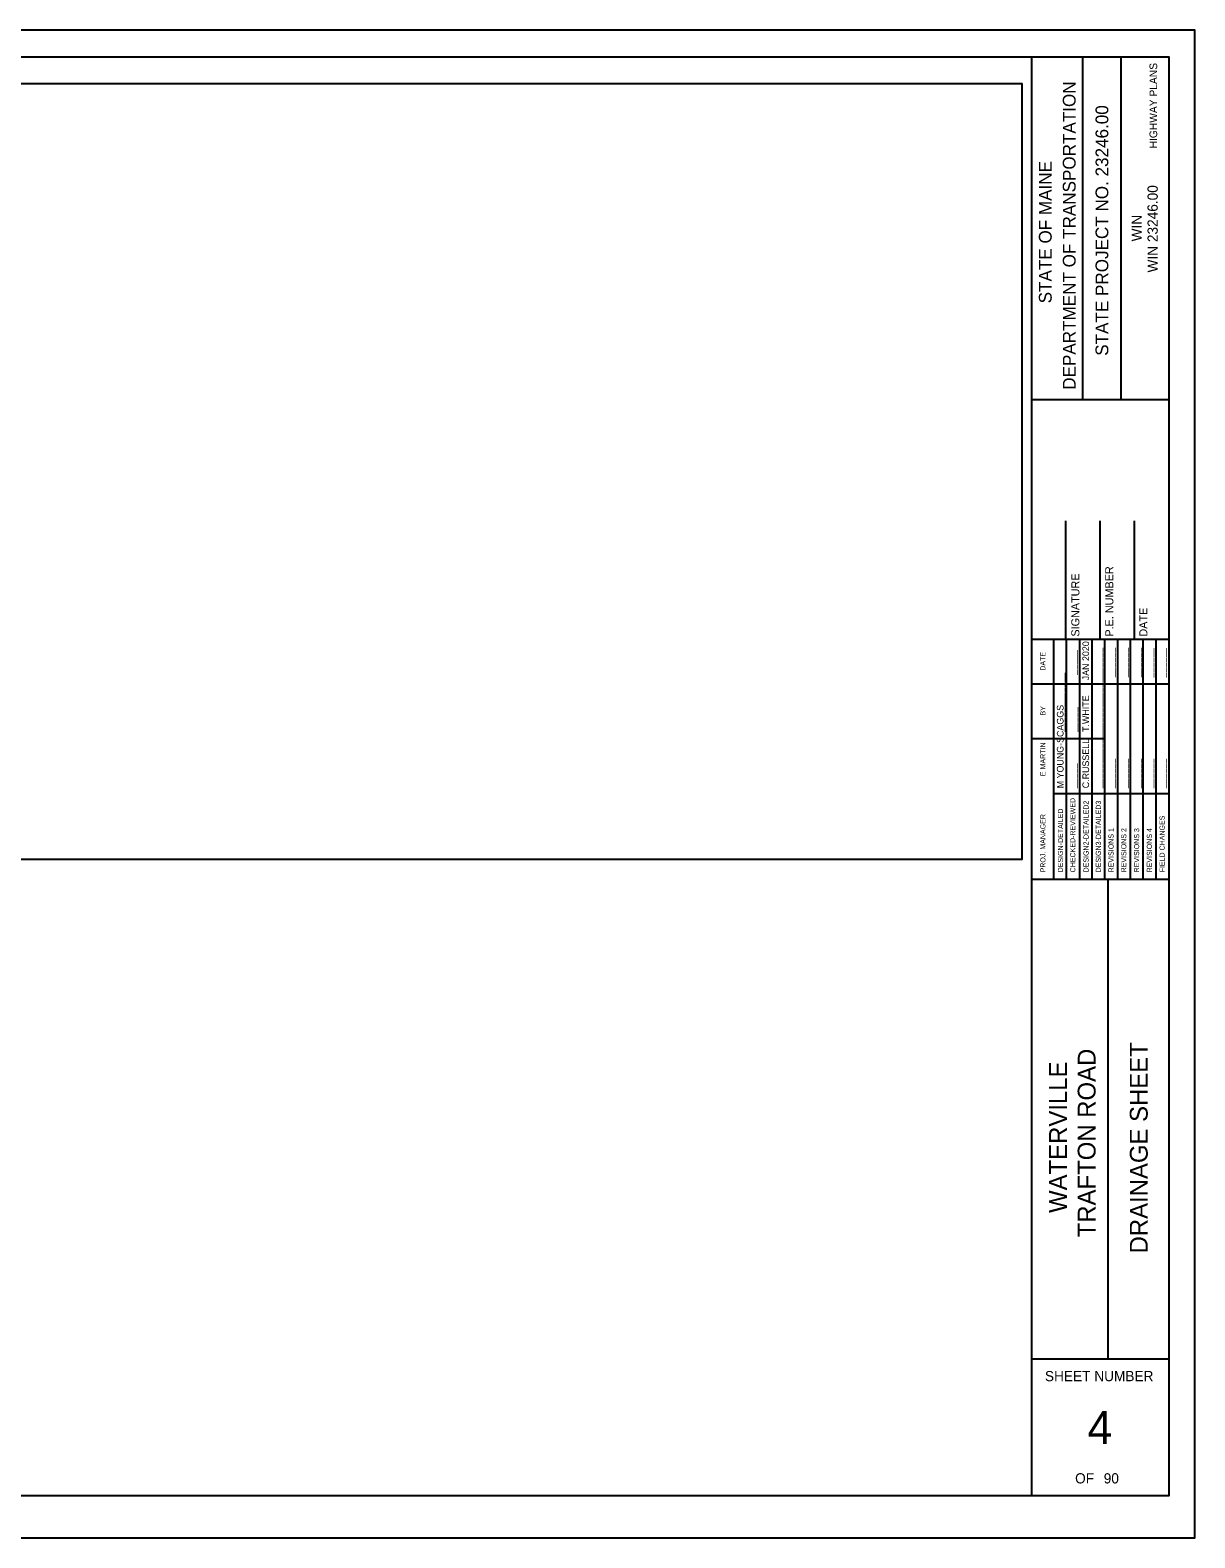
# Model space of a CAD drawing. Extents: x 1146185.75 to 1146188.58, y 612414.35 to 612416.18.
# Drawn here: x 1146187.162 to 1146188.578, y 612414.348 to 612416.182 of the extents above; entities that cross this region are included whole.
import ezdxf

# ---------------------------------------------------------------- set-up
doc = ezdxf.new("R2010")
doc.units = 0
for name, color, linetype in [('BORDER', 7, 'Continuous'), ('Default', 7, 'Continuous'), ('PLOT BOUNDARY', 7, 'Continuous')]:
    doc.layers.add(name, color=color, linetype=linetype)

msp = doc.modelspace()

# ---------------------------------------------------------------- linework, layer by layer
at = {"layer": 'BORDER'}
for p, q in [((1146188.3799, 612414.3994), (1146188.3799, 612416.1494)), ((1146188.442, 612415.7327), (1146188.442, 612416.1494)), ((1146188.4886, 612415.7327), (1146188.4886, 612416.1494)), ((1146188.3799, 612415.7326), (1146188.5466, 612415.7326)), ((1146188.4216, 612415.4411), (1146188.4216, 612415.5853)), ((1146188.4632, 612415.4411), (1146188.4632, 612415.5853)), ((1146188.5049, 612415.4411), (1146188.5049, 612415.5853)), ((1146188.3799, 612415.4411), (1146188.5466, 612415.4411)), ((1146188.3799, 612415.1495), (1146188.5466, 612415.1495)), ((1146188.4731, 612414.5661), (1146188.4731, 612415.1495)), ((1146188.3799, 612414.5661), (1146188.5466, 612414.5661))]:
    msp.add_line(p, q, dxfattribs=at)
msp.add_lwpolyline([(1146185.8799, 612416.1494), (1146188.5466, 612416.1494), (1146188.5466, 612414.3994), (1146185.8799, 612414.3994)], close=True, dxfattribs=at)
for points in [[(1146188.4068, 612415.387), (1146188.4068, 612415.4411)], [(1146188.4224, 612415.1495), (1146188.4224, 612415.4411)], [(1146188.4379, 612415.4411), (1146188.4379, 612415.1495)], [(1146188.4534, 612415.1495), (1146188.4534, 612415.4411)], [(1146188.4689, 612415.1495), (1146188.4689, 612415.4411)], [(1146188.4845, 612415.1495), (1146188.4845, 612415.4411)], [(1146188.5, 612415.1495), (1146188.5, 612415.4411)], [(1146188.5155, 612415.1495), (1146188.5155, 612415.4411)], [(1146188.5311, 612415.1495), (1146188.5311, 612415.4411)], [(1146188.4068, 612415.1495), (1146188.4068, 612415.4294)], [(1146188.3799, 612415.387), (1146188.5466, 612415.387)], [(1146188.3799, 612415.3203), (1146188.4068, 612415.3203)], [(1146188.4068, 612415.3203), (1146188.4689, 612415.3203)], [(1146188.4068, 612415.2536), (1146188.5466, 612415.2536)]]:
    msp.add_lwpolyline(points, dxfattribs=at)
at = {"layer": 'Default'}
msp.add_lwpolyline([(1146185.8819, 612415.1738), (1146188.3682, 612415.1738), (1146188.3682, 612416.1163), (1146185.8819, 612416.1163)], close=True, dxfattribs=at)
at = {"layer": 'PLOT BOUNDARY'}
msp.add_lwpolyline([(1146185.745, 612414.3484), (1146188.5783, 612414.3484), (1146188.5783, 612416.1818), (1146185.745, 612416.1818)], close=True, dxfattribs=at)

# ---------------------------------------------------------------- texts
at = {"layer": 'BORDER'}
for s, height, p in [('HIGHWAY PLANS', 0.009317, (1146188.5325, 612416.038)), ('DEPARTMENT OF TRANSPORTATION', 0.015529, (1146188.4333, 612415.7445)), ('STATE PROJECT NO. 23246.00', 0.015529, (1146188.4731, 612415.7858)), ('STATE OF MAINE', 0.015529, (1146188.4042, 612415.8496)), ('WIN 23246.00', 0.012421, (1146188.5332, 612415.8871)), ('WIN', 0.01242, (1146188.5138, 612415.9249)), ('P.E. NUMBER', 0.009843, (1146188.4792, 612415.4443)), ('SIGNATURE', 0.00984, (1146188.4379, 612415.4443)), ('DATE', 0.00984, (1146188.5206, 612415.4443)), ('JAN 2020', 0.00808, (1146188.4497, 612415.3912)), ('______', 0.00808, (1146188.4646, 612415.3949)), ('______', 0.00808, (1146188.4801, 612415.3949)), ('______', 0.00808, (1146188.4956, 612415.3949)), ('______', 0.00808, (1146188.5112, 612415.3949)), ('______', 0.00808, (1146188.5267, 612415.3944)), ('______', 0.00808, (1146188.5422, 612415.3944)), ('DATE', 0.00619, (1146188.3966, 612415.4029)), ('_____', 0.00808, (1146188.4335, 612415.3979)), ('____________', 0.008076, (1146188.4186, 612415.3284)), ('____________', 0.008076, (1146188.4646, 612415.3284)), ('BY', 0.00619, (1146188.3966, 612415.3484)), ('M YOUNG-SCAGGS', 0.008076, (1146188.4186, 612415.2599)), ('_____', 0.00808, (1146188.4341, 612415.3284)), ('T.WHITE', 0.00808, (1146188.4497, 612415.3284)), ('____________', 0.008076, (1146188.4646, 612415.2599)), ('E MARTIN', 0.00621, (1146188.3966, 612415.2747)), ('C.RUSSELL', 0.00808, (1146188.4497, 612415.2599)), ('_____', 0.00808, (1146188.4335, 612415.2599)), ('______', 0.00808, (1146188.4801, 612415.2599)), ('______', 0.00808, (1146188.4956, 612415.2599)), ('______', 0.00808, (1146188.5112, 612415.2599)), ('______', 0.00808, (1146188.5267, 612415.2599)), ('______', 0.00808, (1146188.5422, 612415.2599)), ('DESIGN-DETAILED', 0.006212, (1146188.418, 612415.1576)), ('CHECKED-REVIEWED', 0.006212, (1146188.4329, 612415.1576)), ('DESIGN2-DETAILED2', 0.006212, (1146188.4491, 612415.1576)), ('DESIGN3-DETAILED3', 0.006212, (1146188.464, 612415.1576)), ('PROJ. MANAGER', 0.006212, (1146188.3966, 612415.1576)), ('FIELD CHANGES', 0.006212, (1146188.5416, 612415.1576)), ('REVISIONS 1', 0.006212, (1146188.4795, 612415.1576)), ('REVISIONS 2', 0.006212, (1146188.495, 612415.1576)), ('REVISIONS 3', 0.006212, (1146188.5106, 612415.1576)), ('REVISIONS 4', 0.006212, (1146188.5261, 612415.1576)), ('TRAFTON ROAD', 0.021738, (1146188.4576, 612414.7139)), ('DRAINAGE SHEET', 0.021738, (1146188.521, 612414.6943)), ('WATERVILLE', 0.02174, (1146188.4228, 612414.7435))]:
    msp.add_text(s, height=height, rotation=90, dxfattribs=at).set_placement(p)
for s, height, p in [('SHEET NUMBER', 0.012421, (1146188.396, 612414.5389)), ('4', 0.0403, (1146188.4478, 612414.4625)), ('OF', 0.01242, (1146188.4327, 612414.4146)), ('90', 0.01242, (1146188.4675, 612414.4146))]:
    msp.add_text(s, height=height, dxfattribs=at).set_placement(p)

doc.saveas('drawing.dxf')
